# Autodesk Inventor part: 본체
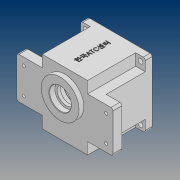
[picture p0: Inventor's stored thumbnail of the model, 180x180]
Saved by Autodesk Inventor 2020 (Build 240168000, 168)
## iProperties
Created: 2020-07
Part Number: 본체
Material: 일반
Document SubType Name: Modeling
Designer: PC312-
Density: 1 g/cm^3
Appearance: 기본값
Mass: 327.743 g
Surface Area: 797.219 cm^2
Volume: 327.743 cm^3
Author: PC312-
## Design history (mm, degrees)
sketch "스케치1"
  geometry: L1 (47, -47)-(-47, -47); L2 (-47, -47)-(-47, 47); L3 (-47, 47)-(47, 47); L4 (47, 47)-(47, -47); L5 (47, -47)-(-47, 47); L6 (-47, -47)-(47, 47); 1 further point
  constraints: 12 end point, 2 midpoint, 2 parallel, 1 horizontal, 1 perpendicular
  dimensions: "d0" = 94 distance of L2.end L3.end; "d1" = 94 distance of L1.end L2.end
extrude "돌출1" new body sketch "스케치1" distance "d2" = 67; taper "d3" = 0 deg
sketch "스케치2"
  geometry: L1 (-33, 30)-(-70, 30); L2 (-70, 30)-(-70, -30); L3 (-70, -30)-(-33, -30); L4 (-33, -30)-(-33, -47); L5 (-33, -47)-(33, -47); L6 (33, -47)-(33, -30); L7 (33, -30)-(70, -30); L8 (70, -30)-(70, 30); L9 (70, 30)-(33, 30); L10 (-33, 30)-(-33, 47); L11 (-33, 47)-(33, 47); L12 (33, 47)-(33, 30); L13 (47, 47)-(-47, 47) reference; L14 (-47, -47)-(47, -47) reference; L15 (0, 0)-(0, 77.106); L16 (0, 0)-(86.58, 0)
  constraints: 28 end point, 7 vertical, 5 horizontal, 5 point on line, 3 collinear, 3 other
  dimensions: "d4" = 140 distance between parallel lines of L2 L8; "d5" = 60 distance of L7.end L8.end; "d6" = 66 distance of L10.end L11.end
extrude "돌출2" join sketch "스케치2" distance "d7" = 13; taper "d8" = 0 deg
sketch "스케치3"
  geometry: L1 (-33, 30)-(-33, 47) reference; L2 (-33, 47)-(-47, 47) reference; L3 (-47, 47)-(-47, 30) reference; L4 (-47, 30)-(-33, 30) reference; L5 (33, 30)-(47, 30) reference; L6 (47, 30)-(47, 47) reference; L7 (47, 47)-(33, 47) reference; L8 (33, 47)-(33, 30) reference; L9 (-33, -47)-(-33, -30) reference; L10 (-33, -30)-(-47, -30) reference; L11 (-47, -30)-(-47, -47) reference; L12 (-47, -47)-(-33, -47) reference; L13 (47, -30)-(33, -30) reference; L14 (33, -30)-(33, -47) reference; L15 (33, -47)-(47, -47) reference; L16 (47, -47)-(47, -30) reference; 1 further point
extrude "돌출3" cut sketch "스케치3" distance "d9" = 57; taper "d10" = 0 deg
sketch "스케치4"
  geometry: L1 (0, 0)-(0, 66.5); L2 (0, 0)-(92.931, 0); 4 further points
  constraints: 4 end point, 2 symmetric about line, 1 horizontal, 1 horizontal alignment, 1 vertical, 1 vertical alignment
  dimensions: "d18" = 80 distance of point (40, 40) point (-40, 40); "d19" = 80 distance of point (40, -40) point (40, 40)
hole "구멍1" sketch "스케치4" at (40, 40), (40, -40), (-40, 40), (-40, -40) diameter "d11" = 7; stored, may be unused: countersink angle "d15" = 90 deg, drill point angle "d17" = 0 deg; dims "d12" = 8, "d13" = 4, "d14" = 2, "d16" = 10
sketch "스케치5"
  geometry: C1 r 27.5 at (0, 11); 1 further point
  constraints: 1 centre point, 1 vertical alignment
  dimensions: "d20" = 11 distance of point (0, 0) C1.centre; "d21" = 55 diameter of C1
extrude "돌출4" join sketch "스케치5" distance "d22" = 7; taper "d23" = 0 deg
sketch "스케치6"
  geometry: L1 (0, 0)-(0, 65.994); L2 (0, 0)-(-103.188, 0); 4 further points
  constraints: 4 end point, 2 symmetric about line, 1 horizontal, 1 horizontal alignment, 1 vertical, 1 vertical alignment
  dimensions: "d31" = 38 distance of point (-60, -19) point (-60, 19); "d32" = 120 distance of point (60, 19) point (-60, 19)
hole "구멍2" sketch "스케치6" at (60, 19), (60, -19), (-60, 19), (-60, -19) diameter "d24" = 4.5; stored, may be unused: countersink angle "d28" = 90 deg, drill point angle "d30" = 0 deg; dims "d25" = 8, "d26" = 10, "d27" = 5, "d29" = 10
sketch "스케치7"
  geometry: C1 r 43 at (0, 0); 1 further point
  constraints: 1 centre point, 1 coincident
  dimensions: "d33" = 86 diameter of C1
extrude "돌출5" cut sketch "스케치7" distance "d34" = 9; taper "d35" = 0 deg
sketch "스케치9"
  geometry: 2 further points
  constraints: 1 coincident
hole "구멍3" sketch "스케치9" at (0, 0) diameter "d36" = 80; stored, may be unused: countersink angle "d40" = 90 deg, drill point angle "d42" = 0 deg; dims "d37" = 8, "d38" = 10, "d39" = 5, "d41" = 62
sketch "스케치10"
  geometry: C1 r 27.5 at (0, 0) reference; 2 further points
  constraints: 1 coincident
hole "구멍4" sketch "스케치10" at (0, 0) diameter "d43" = 25; stored, may be unused: countersink angle "d47" = 90 deg, drill point angle "d49" = 0 deg; dims "d44" = 8, "d45" = 32, "d46" = 8.3, "d48" = 62
sketch "스케치11"
  geometry: C1 r 12.5 at (0, 11) reference; A1 r 21 centre (0, 11) between (8.978, -7.984) and (-8.978, -7.984); A2 r 15 centre (0, -20) between (-8.978, -7.984) and (8.978, -7.984); 1 further point
  constraints: 4 point on circle, 2 centre point, 1 coincident, 1 vertical alignment
  dimensions: "d52" = 20 distance of A2.centre point (0, 0); "d53" = 21 radius of A1; "d54" = 15 radius of A2
extrude "돌출6" join sketch "스케치11" distance "d55" = 7; taper "d56" = 0 deg
sketch "스케치12"
  geometry: A1 r 15 centre (0, -20) between (-8.978, -7.984) and (8.978, -7.984) reference; 2 further points
  constraints: 1 coincident
hole "구멍5" sketch "스케치12" at (0, -20) diameter "d57" = 19; stored, may be unused: countersink angle "d61" = 90 deg, drill point angle "d63" = 0 deg; dims "d58" = 8, "d59" = 22, "d60" = 7, "d62" = 10
sketch "스케치13"
  geometry: C1 r 12.5 at (0, 11) reference; 2 further points
  constraints: 1 coincident
hole "구멍6" sketch "스케치13" at (0, 11) diameter "d64" = 35; stored, may be unused: countersink angle "d68" = 90 deg, drill point angle "d70" = 0 deg; dims "d65" = 8, "d66" = 22, "d67" = 7, "d69" = 10
sketch "스케치14"
  geometry: L1 (35.777, 4)-(39.799, 4); L2 (35.777, -4)-(39.799, -4); A1 r 4 centre (36, 0) between (36, 4) and (36, -4); A2 r 36 centre (0, 0) between (36, 0) and (35.777, 4); A3 r 40 centre (0, 0) between (39.799, -4) and (39.799, 4) reference; 1 further point
  constraints: 7 point on circle, 4 end point, 2 centre point, 2 horizontal, 2 point on line, 2 tangent, 1 coincident, 1 horizontal alignment
  dimensions: "d71" = 8 diameter of A1; "d72" = 72 diameter of A2
extrude "돌출7" join sketch "스케치14" stored distance "d73" = 7; taper "d74" = 0 deg
sketch "스케치15"
  geometry: A1 r 4 centre (36, 0) between (36, 4) and (36, -4) reference; 2 further points
  constraints: 1 coincident
hole "구멍7" sketch "스케치15" at (36, 0) diameter "d75" = 3.242; stored, may be unused: countersink angle "d79" = 90 deg, drill point angle "d81" = 118 deg; dims "d76" = 7, "d77" = 22, "d78" = 7, "d80" = 9
chamfer "모따기1" distance "d85" = 0.8; stored, may be unused: second distance "d86" = 2, angle "d87" = 30 deg
fillet "모깎기1" dims "d88" = 3
fillet "모깎기2" dims "d89" = 3
fillet "모깎기3" dims "d90" = 3
chamfer "모따기2" distance "d91" = 1; stored, may be unused: second distance "d92" = 2, angle "d93" = 30 deg
node "작업 평면1"
sketch "스케치16"
  geometry: L1 (77, 80)-(-11, 80) reference; 2 further points
  constraints: 1 vertical alignment, 1 other
  dimensions: "d95" = 40 distance from line of point (33, 40) L1
feature "엠보싱1" sketch "스케치16" dims "d0" = 94, "d1" = 94, "d96" = 0.5, "d97" = 0
node "솔리드1"
pattern_circular "원형 패턴1" dims angle "d83" = 360 deg
node "투영된 루프1"
node "투영된 루프2"
node "투영된 루프3"
node "투영된 루프4"
feature "A9D066F2-1C7D-4E18-AEED-F7BC21143FA4" dims "d11" = 7, "d12" = 8, "d13" = 4, "d14" = 2, "d15" = 90 deg, "d16" = 10, "d17" = 0
other parameters: "d94" = 1
